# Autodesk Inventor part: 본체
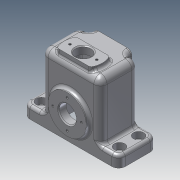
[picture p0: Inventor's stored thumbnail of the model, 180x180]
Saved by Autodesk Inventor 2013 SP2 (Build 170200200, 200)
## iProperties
Created: 2023-12
Part Number: 본체
Material: 알루미늄 6061
Document SubType Name: Modeling
Designer: i
Density: 2.71 g/cm^3
Mass: 219.65 g
Surface Area: 359.947 cm^2
Volume: 81.0516 cm^3
Author: i
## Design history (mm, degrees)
sketch "스케치1"
  geometry: L1 (-31, 20)-(31, 20); L2 (31, 20)-(31, -20); L3 (31, -20)-(-31, -20); L4 (-31, -20)-(-31, 20); L5 (-31, 20)-(31, -20); L6 (31, 20)-(-31, -20); 1 further point
  constraints: 12 end point, 2 midpoint, 2 parallel, 1 horizontal, 1 perpendicular
  dimensions: "d0" = 62 distance of L2.end L3.end; "d1" = 40 distance of L1.end L2.end
extrude "돌출1" new body sketch "스케치1" distance "d2" = 72; taper "d3" = 0 deg
feature "쉘1" dims "d4" = 4
sketch "스케치2"
  geometry: L1 (62, 0)-(0, 0) reference; C1 r 20 at (31, 28); 2 further points
  constraints: 1 centre point, 1 midpoint, 1 vertical alignment
  dimensions: "d5" = 40 diameter of C1; "d6" = 28 distance from line of L1 C1.centre
extrude "돌출2" join sketch "스케치2" distance "d7" = 4; taper "d8" = 0 deg
sketch "스케치3"
  geometry: L1 (62, 0)-(0, 0) reference; C1 r 12 at (31, 28); 2 further points
  constraints: 1 centre point, 1 midpoint, 1 vertical alignment
  dimensions: "d9" = 24 diameter of C1; "d10" = 28 distance from line of L1 C1.centre
extrude "돌출3" join sketch "스케치3" distance "d11" = 4; taper "d12" = 0 deg
sketch "스케치4"
  geometry: L1 (62, 0)-(0, 0) reference; L2 (0, 72)-(62, 72) reference; L3 (11, 72)-(51, 72); L4 (51, 72)-(51, 48); L5 (51, 48)-(11, 48); L6 (11, 48)-(11, 72); 3 further points
  constraints: 8 end point, 3 midpoint, 2 parallel, 1 horizontal, 1 perpendicular, 1 vertical alignment
  dimensions: "d13" = 40 distance of L4.end L5.end; "d15" = 24 distance of L5.end L3.start
extrude "돌출4" join sketch "스케치4" distance "d16" = 4; taper "d17" = 0 deg
sketch "스케치5"
  geometry: L1 (31, 20)-(-31, 20) reference; L2 (-31, 20)-(-31, -20) reference; L3 (-31, -20)-(31, -20) reference; L4 (31, -20)-(31, 20) reference; L5 (50, 20)-(-50, 20); L6 (-50, 20)-(-50, -20); L7 (-50, -20)-(50, -20); L8 (50, -20)-(50, 20); L9 (50, 20)-(-50, -20); L10 (-50, 20)-(50, -20); 1 further point
  constraints: 12 end point, 2 midpoint, 2 parallel, 1 horizontal, 1 perpendicular
  dimensions: "d18" = 100 distance of L7.end L6.end; "d19" = 40 distance of L6.end L5.end
extrude "돌출5" join sketch "스케치5" distance "d20" = 12; taper "d21" = 0 deg
sketch "스케치6"
  geometry: L1 (-31, -20)-(31, -20) reference; L2 (-20, 24)-(20, 24) reference; L3 (-20, -17)-(-17.321, -17); L4 (20, -17)-(20, 3); L5 (20, 3)-(17.321, 3); L6 (-20, 3)-(-20, -17); L7 (-20, -7)-(20, -7); L8 (17.321, 3)-(-17.321, 3); L9 (17.321, -17)-(20, -17); L10 (-17.321, -17)-(17.321, -17); L11 (-17.321, 3)-(-20, 3); A1 r 20 centre (0, -7) between (-17.321, 3) and (-17.321, -17); A2 r 20 centre (0, -7) between (17.321, 3) and (-17.321, 3); A3 r 20 centre (0, -7) between (15.199, -20) and (17.321, 3); A4 r 20 centre (0, -7) between (-17.321, -17) and (15.199, -20); 2 further points
  constraints: 18 end point, 10 parallel, 9 point on circle, 4 centre point, 3 horizontal, 3 midpoint, 3 perpendicular, 2 point on line, 1 coincident, 1 vertical alignment
  dimensions: "d22" = 31 distance from line of L2 L7.start; "d23" = 20 distance of L6.start L3.start; "d24" = 40 diameter of A1; "d25" = 40 distance of L4.end L6.start
extrude "돌출6" join sketch "스케치6" distance "d26" = 4; taper "d27" = 0 deg
sketch "스케치7"
  geometry: C1 r 8 at (0, -7); A1 r 20 centre (0, -7) between (-17.321, 3) and (-17.321, -17) reference; 1 further point
  constraints: 1 centre point, 1 coincident
  dimensions: "d28" = 16 diameter of C1
extrude "돌출7" cut sketch "스케치7" stored distance "d29" = 4; taper "d30" = 0 deg
sketch "스케치8"
  geometry: C1 r 12 at (0, 0) reference; 2 further points
  constraints: 1 coincident
hole "구멍1" sketch "스케치8" at (0, 0) diameter "d31" = 14.917; stored, may be unused: countersink angle "d35" = 90 deg, drill point angle "d37" = 0 deg; dims "d32" = 6, "d33" = 4, "d34" = 2, "d36" = 8
sketch "스케치9"
  geometry: C1 r 20 at (0, 0) reference; 2 further points
  constraints: 1 coincident
hole "구멍2" sketch "스케치9" at (0, 0) diameter "d38" = 18; stored, may be unused: countersink angle "d42" = 90 deg, drill point angle "d44" = 0 deg; dims "d39" = 6, "d40" = 4, "d41" = 2, "d43" = 8
sketch "스케치10"
  geometry: C1 r 8 at (0, -7) reference; 3 further points
  constraints: 2 horizontal alignment
  dimensions: "d45" = 28 distance of point (-14, -7) point (14, -7); "d47" = 14 distance of C1.centre point (-14, -7)
hole "구멍3" sketch "스케치10" at (-14, -7), (14, -7) diameter "d48" = 2.459; stored, may be unused: countersink angle "d52" = 90 deg, drill point angle "d54" = 0 deg; dims "d49" = 6, "d50" = 4, "d51" = 2, "d53" = 8
sketch "스케치11"
  geometry: L1 (51, 72)-(11, 72) reference; 3 further points
  constraints: 1 horizontal alignment
  dimensions: "d55" = 6 distance from line of point (17, 66) L1; "d56" = 28 distance of point (45, 66) point (17, 66); "d57" = 14 horizontal distance of point (31, 0) point (17, 66)
hole "구멍4" sketch "스케치11" at (17, 66), (45, 66) diameter "d58" = 2.459; stored, may be unused: countersink angle "d62" = 90 deg, drill point angle "d64" = 0 deg; dims "d59" = 6, "d60" = 4, "d61" = 2, "d63" = 8
sketch "스케치12" dims "d65" = 30
  geometry: C1 r 9 at (0, 0) reference; C2 r 20 at (0, 0) reference; 3 further points
  constraints: 2 vertical alignment, 1 coincident, 2 other
hole "구멍5" sketch "스케치12" at (0, 15) diameter "d66" = 2.459; stored, may be unused: countersink angle "d70" = 90 deg, drill point angle "d72" = 0 deg; dims "d67" = 6, "d68" = 4, "d69" = 2, "d71" = 8
chamfer "모따기1" distance "d88" = 1; stored, may be unused: second distance "d89" = 2, angle "d90" = 45 deg
fillet "모깎기8" dims "d93" = 7
fillet "모깎기9" dims "d94" = 3
fillet "모깎기10" dims "d95" = 7
fillet "모깎기11" dims "d96" = 3
fillet "모깎기15" dims "d100" = 7
fillet "모깎기16" dims "d101" = 3
fillet "모깎기17" dims "d102" = 7
fillet "모깎기23" dims "d108" = 5
fillet "모깎기19" dims "d104" = 3
fillet "모깎기20" dims "d105" = 3
fillet "모깎기21" dims "d106" = 3
fillet "모깎기22" dims "d107" = 5
fillet "모깎기24" dims "d109" = 3
fillet "모깎기25" dims "d110" = 3
fillet "모깎기26" dims "d111" = 3
sketch "스케치14"
  geometry: L1 (26, -15)-(0, -15) reference; L2 (-11, 25)-(-11, 1) reference; 2 further points
  constraints: 1 other
  dimensions: "d112" = 40 distance from line of L1 point (12, 25); "d113" = 23 distance from line of L2 point (12, 25)
feature "엠보싱1" sketch "스케치14" dims "d114" = 0.5, "d115" = 0
fillet "모깎기27" dims "d116" = 3
sketch "스케치15"
  geometry: L1 (33.165, 17)-(43, 17) reference; L2 (34, -13)-(34, 13) reference; L3 (43, -17)-(33.165, -17) reference; L4 (47, 13)-(47, -13) reference; L5 (-43, -20)-(-33.165, -20) reference; A1 r 10 centre (24, 13) between (34, 13) and (33.165, 17) reference; A2 r 10 centre (24, -13) between (33.165, -17) and (34, -13) reference; A3 r 4 centre (43, -13) between (43, -17) and (47, -13) reference; A4 r 4 centre (43, 13) between (47, 13) and (43, 17) reference; 5 further points
  constraints: 2 horizontal alignment, 2 vertical alignment
  dimensions: "d117" = 82 distance of point (41, 10) point (-41, 10); "d119" = 20 distance of point (-41, -10) point (-41, 10); "d120" = 10 distance from line of L5 point (-41, -10); "d121" = 41 horizontal distance of point (0, 0) point (-41, 10)
hole "구멍7" sketch "스케치15" at (-41, 10), (-41, -10), (41, 10), (41, -10) diameter "d122" = 6.6; stored, may be unused: countersink angle "d126" = 90 deg, drill point angle "d128" = 0 deg; dims "d123" = 6, "d124" = 11, "d125" = 6.6, "d127" = 8
node "솔리드1"
pattern_circular "원형 패턴1" dims angle "d74" = 360 deg
node "투영된 루프2"
